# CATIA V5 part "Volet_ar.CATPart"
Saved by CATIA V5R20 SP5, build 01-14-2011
Part number: Skl_Volet_ar
Publications: "Plan xy", "Axe_pivot_vol_ar/gouv", "Axe_glissiere_vol_ar/bras_ar"
Bounding box of the stored display mesh (mm): x 0 to 0, y 0 to 152.727, z -1100 to 0
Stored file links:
  U:\2A\CFAO\dossier sans titre\Volet_ar.CATPart
  U:\2A\CFAO\dossier sans titre\Skl_gouvernail.CATProduct
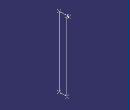
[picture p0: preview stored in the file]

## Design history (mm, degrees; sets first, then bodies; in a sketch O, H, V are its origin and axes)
Set1
  Point1 to Point5: linked copy from another document
Body1 (main body)
  Line1: type PtPt, FirstPoint Point1, SecondPoint Point2
  Line2 "Axe_pivot_vol_ar/gouv": type PtPt, FirstPoint Point2, SecondPoint Point3
  Line3: type PtPt, FirstPoint Point3, SecondPoint Point4
  Line4: type PtPt, FirstPoint Point1, SecondPoint Point4
  Line5 "Axe_glissiere_vol_ar/bras_ar": type PtPt, FirstPoint Point5, SecondPoint Point2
